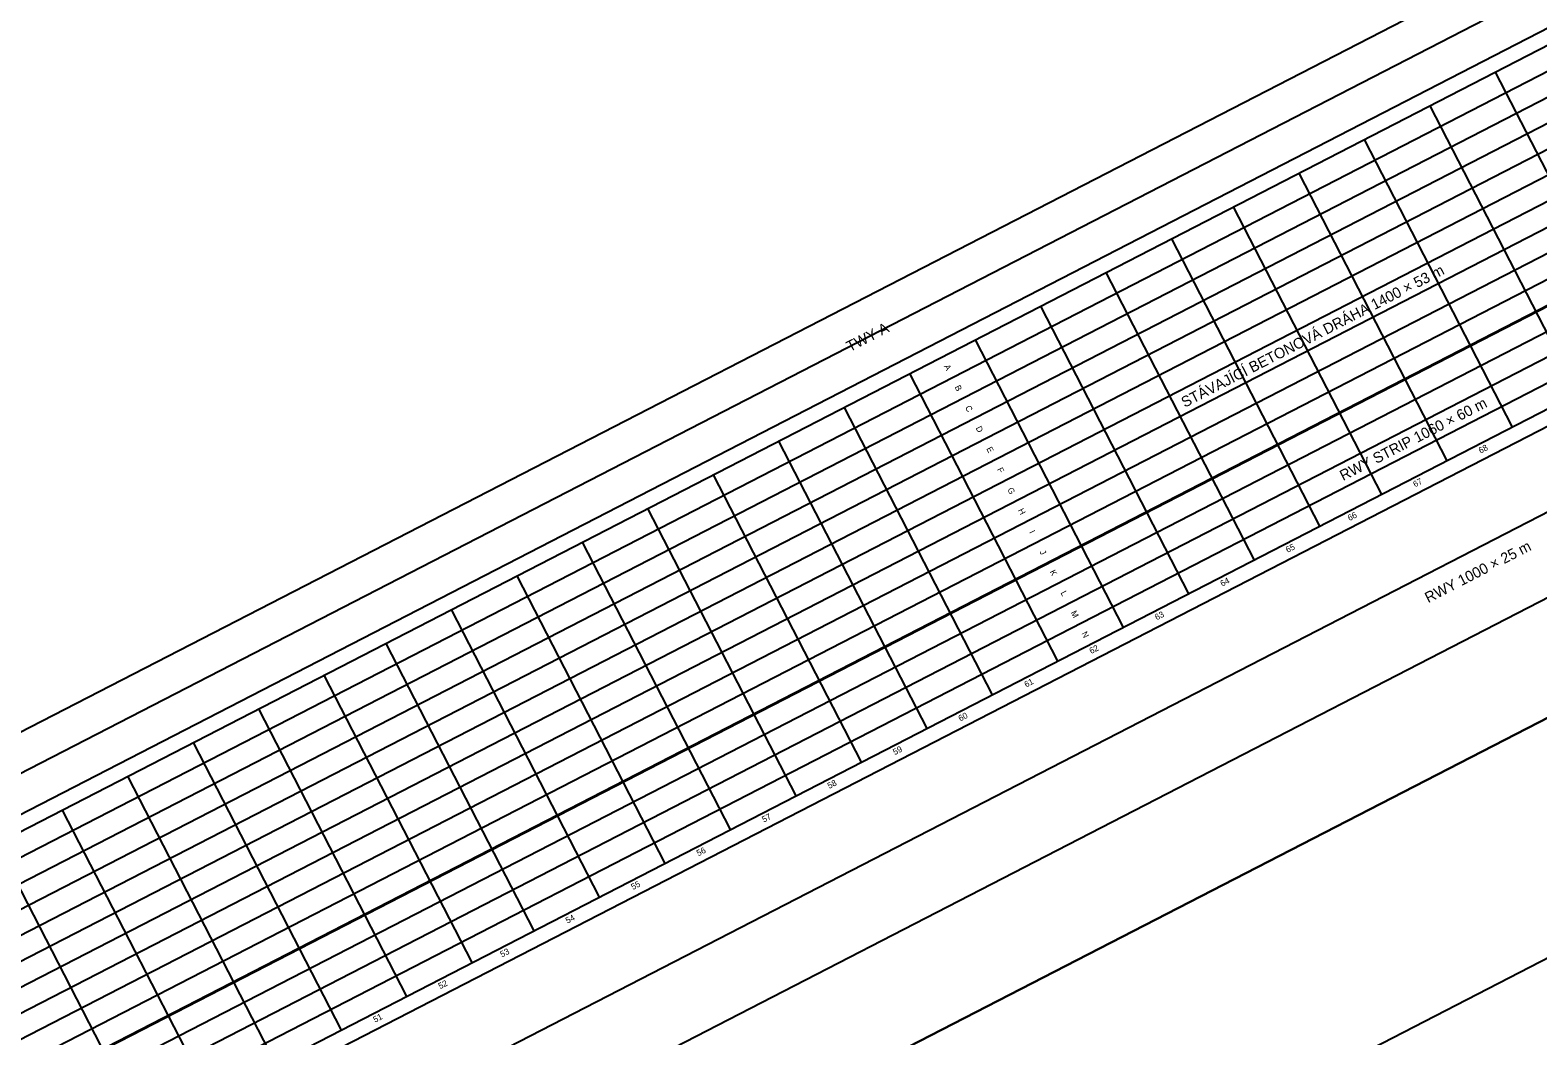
# Model space of a CAD drawing. Extents: x -886320 to -884760, y -1024172 to -1023483.
# Drawn here: x -885521.7 to -885274.6, y -1023897 to -1023732.2 of the extents above; entities that cross this region are included whole.
import ezdxf

# ---------------------------------------------------------------- set-up
doc = ezdxf.new("R2010")
doc.units = 0
for name, color, linetype in [('AGA__Netisknout', 7, 'Continuous'), ('Stavajici_betonova_draha', 7, 'Continuous'), ('Stavajici_betonova_draha_osa', 7, 'Continuous'), ('Stavajici_betonova_draha_popis', 7, 'Continuous'), ('Stavajici_betonova_draha_Popis desky', 7, 'Continuous'), ('Stavajici_betonova_draha_Spára', 7, 'Continuous'), ('Stavajici_drahovy_system', 7, 'Continuous'), ('Stavajici_drahovy_system_osy', 7, 'Continuous'), ('Stavajici_drahovy_system_popis', 7, 'Continuous'), ('Stavajici_drahovy_system_RWY_strip', 7, 'Continuous'), ('Stavajici_drahovy_system_TWY', 7, 'Continuous'), ('Stavajici_drahovy_system_TWY_osy', 7, 'Continuous'), ('Stavajici_drahovy_system_TWY_popis', 7, 'Continuous')]:
    doc.layers.add(name, color=color, linetype=linetype)

msp = doc.modelspace()

# ---------------------------------------------------------------- linework, layer by layer
at = {"layer": 'AGA__Netisknout'}
msp.add_line((-886017.78, -1024147.99), (-884773.13, -1023507.02), dxfattribs=at)
at = {"layer": 'Stavajici_betonova_draha'}
for p, q in [((-886029.69, -1024124.32), (-884785.04, -1023483.35)), ((-886029.69, -1024124.32), (-884785.04, -1023483.35)), ((-886005.42, -1024171.44), (-884760.77, -1023530.47)), ((-886005.42, -1024171.44), (-884760.77, -1023530.47))]:
    msp.add_line(p, q, dxfattribs=at)
at = {"layer": 'Stavajici_betonova_draha_osa'}
msp.add_line((-886017.55, -1024147.88), (-884772.9, -1023506.91), dxfattribs=at)
at = {"layer": 'Stavajici_betonova_draha_Spára'}
for p, q in [((-886029.91, -1024124.43), (-884785.26, -1023483.46)), ((-886028.18, -1024127.8), (-884783.53, -1023486.82)), ((-886026.44, -1024131.16), (-884781.79, -1023490.19)), ((-886024.71, -1024134.53), (-884780.06, -1023493.56)), ((-886022.98, -1024137.89), (-884778.33, -1023496.92)), ((-886021.24, -1024141.26), (-884776.59, -1023500.29)), ((-886019.51, -1024144.63), (-884774.86, -1023503.65)), ((-886016.04, -1024151.36), (-884771.39, -1023510.39)), ((-886014.31, -1024154.72), (-884769.66, -1023513.75)), ((-886012.58, -1024158.09), (-884767.93, -1023517.12)), ((-886010.84, -1024161.46), (-884766.19, -1023520.48)), ((-886009.11, -1024164.82), (-884764.46, -1023523.85)), ((-886007.38, -1024168.19), (-884762.73, -1023527.21)), ((-886005.64, -1024171.55), (-884760.99, -1023530.58)), ((-885281.6, -1023739.06), (-885257.33, -1023786.19)), ((-885292.33, -1023744.59), (-885268.06, -1023791.71)), ((-885303.06, -1023750.12), (-885278.79, -1023797.24)), ((-885313.79, -1023755.64), (-885289.52, -1023802.76)), ((-885324.52, -1023761.17), (-885300.25, -1023808.29)), ((-885334.66, -1023766.39), (-885310.39, -1023813.51)), ((-885345.39, -1023771.92), (-885321.12, -1023819.04)), ((-885356.12, -1023777.44), (-885331.85, -1023824.56)), ((-885366.85, -1023782.97), (-885342.58, -1023830.09)), ((-885377.58, -1023788.49), (-885353.31, -1023835.61)), ((-885388.31, -1023794.02), (-885364.04, -1023841.14)), ((-885399.04, -1023799.54), (-885374.77, -1023846.67)), ((-885409.77, -1023805.07), (-885385.5, -1023852.19)), ((-885420.5, -1023810.59), (-885396.23, -1023857.72)), ((-885431.23, -1023816.12), (-885406.96, -1023863.24)), ((-885441.96, -1023821.65), (-885417.69, -1023868.77)), ((-885452.69, -1023827.17), (-885428.42, -1023874.29)), ((-885463.42, -1023832.7), (-885439.15, -1023879.82)), ((-885473.55, -1023837.92), (-885449.29, -1023885.04)), ((-885484.28, -1023843.44), (-885460.02, -1023890.57)), ((-885495.01, -1023848.97), (-885470.75, -1023896.09)), ((-885505.74, -1023854.49), (-885481.48, -1023901.62)), ((-885516.47, -1023860.02), (-885492.2, -1023907.14)), ((-885527.2, -1023865.55), (-885502.93, -1023912.67))]:
    msp.add_line(p, q, dxfattribs=at)
at = {"layer": 'Stavajici_drahovy_system'}
for p, q in [((-885721.56, -1024028.07), (-884864.53, -1023586.71)), ((-885726.12, -1024058.54), (-884837.08, -1023600.7)), ((-885744.78, -1024087.83), (-884802.4, -1023602.52)), ((-885728.75, -1024118.95), (-884786.38, -1023633.64))]:
    msp.add_line(p, q, dxfattribs=at)
at = {"layer": 'Stavajici_drahovy_system_osy'}
msp.add_line((-885731.84, -1024047.42), (-884842.81, -1023589.59), dxfattribs=at)
at = {"layer": 'Stavajici_drahovy_system_RWY_strip'}
for p, q in [((-885772.25, -1024034.49), (-884829.87, -1023549.18)), ((-884802.4, -1023602.52), (-885744.78, -1024087.83))]:
    msp.add_line(p, q, dxfattribs=at)
at = {"layer": 'Stavajici_drahovy_system_TWY'}
for p, q in [((-885887.27, -1024034.67), (-884885.91, -1023518.99)), ((-885748.12, -1023976.51), (-884891.09, -1023535.15))]:
    msp.add_line(p, q, dxfattribs=at)
at = {"layer": 'Stavajici_drahovy_system_TWY_osy'}
msp.add_line((-885886.7, -1024041.13), (-884883.17, -1023524.32), dxfattribs=at)

# ---------------------------------------------------------------- texts
at = {"layer": 'Stavajici_betonova_draha_popis'}
msp.add_text('STÁVAJÍCÍ BETONOVÁ DRÁHA 1400 × 53 m', height=1.75, rotation=27.2477, dxfattribs=at).set_placement((-885332.48, -1023794.1))
at = {"layer": 'Stavajici_betonova_draha_Popis desky'}
for s, rotation, p in [('A', 297.2477, (-885371.97, -1023787.3)), ('B', 297.2477, (-885370.22, -1023790.69)), ('C', 297.2477, (-885368.5, -1023794.03)), ('D', 297.2477, (-885366.77, -1023797.4)), ('E', 297.2477, (-885365.02, -1023800.79)), ('68', 27.2477, (-885284.01, -1023801.61)), ('F', 297.2477, (-885363.27, -1023804.18)), ('67', 27.2477, (-885294.74, -1023807.14)), ('G', 297.2477, (-885361.58, -1023807.47)), ('H', 297.2477, (-885359.83, -1023810.88)), ('66', 27.2477, (-885305.47, -1023812.67)), ('I', 297.2477, (-885357.98, -1023814.47)), ('65', 27.2477, (-885315.62, -1023817.89)), ('J', 297.2477, (-885356.3, -1023817.72)), ('K', 297.2477, (-885354.63, -1023820.96)), ('64', 27.2477, (-885326.34, -1023823.41)), ('L', 297.2477, (-885352.86, -1023824.4)), ('M', 297.2477, (-885351.19, -1023827.65)), ('63', 27.2477, (-885337.07, -1023828.94)), ('N', 297.2477, (-885349.43, -1023831.07)), ('62', 27.2477, (-885347.8, -1023834.46)), ('61', 27.2477, (-885358.46, -1023839.95)), ('60', 27.2477, (-885369.26, -1023845.52)), ('59', 27.2477, (-885379.99, -1023851.04)), ('58', 27.2477, (-885390.72, -1023856.57)), ('57', 27.2477, (-885401.45, -1023862.09)), ('56', 27.2477, (-885412.18, -1023867.62)), ('55', 27.2477, (-885422.91, -1023873.15)), ('54', 27.2477, (-885433.64, -1023878.67)), ('53', 27.2477, (-885444.37, -1023884.2)), ('52', 27.2477, (-885454.5, -1023889.41)), ('51', 27.2477, (-885465.17, -1023894.9))]:
    msp.add_text(s, height=1, rotation=rotation, dxfattribs=at).set_placement(p)
at = {"layer": 'Stavajici_drahovy_system_popis'}
msp.add_text('RWY 1000 × 25 m', height=1.75, rotation=27.2477, dxfattribs=at).set_placement((-885292.57, -1023826.13))
at = {"layer": 'Stavajici_drahovy_system_RWY_strip'}
msp.add_text('RWY STRIP 1060 × 60 m', height=1.75, rotation=27.2477, dxfattribs=at).set_placement((-885306.51, -1023806.11))
at = {"layer": 'Stavajici_drahovy_system_TWY_popis'}
msp.add_text('TWY A', height=1.75, rotation=27.2477, dxfattribs=at).set_placement((-885387.36, -1023784.96))

doc.saveas('drawing.dxf')
